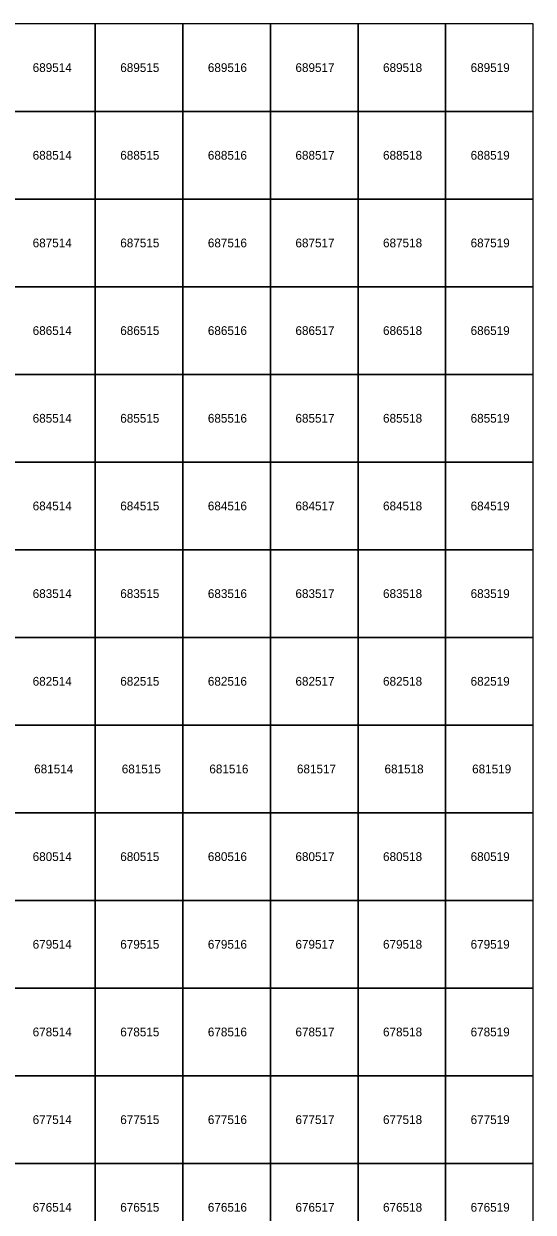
# Model space of a CAD drawing. Extents: x 25485000 to 25520000, y 6656775 to 6690000.
# Drawn here: x 25514183 to 25520000, y 6676444 to 6690000 of the extents above; entities that cross this region are included whole.
import ezdxf

# ---------------------------------------------------------------- set-up
doc = ezdxf.new("R2010")
doc.units = 0
doc.layers.add('Level 63', color=7, linetype='Continuous')

msp = doc.modelspace()

# ---------------------------------------------------------------- linework, layer by layer
at = {"layer": 'Level 63'}
for points in [[(25514000, 6689000), (25515000, 6689000), (25515000, 6690000), (25514000, 6690000)], [(25515000, 6689000), (25516000, 6689000), (25516000, 6690000), (25515000, 6690000)], [(25516000, 6689000), (25517000, 6689000), (25517000, 6690000), (25516000, 6690000)], [(25517000, 6689000), (25518000, 6689000), (25518000, 6690000), (25517000, 6690000)], [(25518000, 6689000), (25519000, 6689000), (25519000, 6690000), (25518000, 6690000)], [(25519000, 6689000), (25520000, 6689000), (25520000, 6690000), (25519000, 6690000)], [(25514000, 6688000), (25515000, 6688000), (25515000, 6689000), (25514000, 6689000)], [(25515000, 6688000), (25516000, 6688000), (25516000, 6689000), (25515000, 6689000)], [(25516000, 6688000), (25517000, 6688000), (25517000, 6689000), (25516000, 6689000)], [(25517000, 6688000), (25518000, 6688000), (25518000, 6689000), (25517000, 6689000)], [(25518000, 6688000), (25519000, 6688000), (25519000, 6689000), (25518000, 6689000)], [(25519000, 6688000), (25520000, 6688000), (25520000, 6689000), (25519000, 6689000)], [(25514000, 6687000), (25515000, 6687000), (25515000, 6688000), (25514000, 6688000)], [(25515000, 6687000), (25516000, 6687000), (25516000, 6688000), (25515000, 6688000)], [(25516000, 6687000), (25517000, 6687000), (25517000, 6688000), (25516000, 6688000)], [(25517000, 6687000), (25518000, 6687000), (25518000, 6688000), (25517000, 6688000)], [(25518000, 6687000), (25519000, 6687000), (25519000, 6688000), (25518000, 6688000)], [(25519000, 6687000), (25520000, 6687000), (25520000, 6688000), (25519000, 6688000)], [(25514000, 6686000), (25515000, 6686000), (25515000, 6687000), (25514000, 6687000)], [(25515000, 6686000), (25516000, 6686000), (25516000, 6687000), (25515000, 6687000)], [(25516000, 6686000), (25517000, 6686000), (25517000, 6687000), (25516000, 6687000)], [(25517000, 6686000), (25518000, 6686000), (25518000, 6687000), (25517000, 6687000)], [(25518000, 6686000), (25519000, 6686000), (25519000, 6687000), (25518000, 6687000)], [(25519000, 6686000), (25520000, 6686000), (25520000, 6687000), (25519000, 6687000)], [(25514000, 6685000), (25515000, 6685000), (25515000, 6686000), (25514000, 6686000)], [(25515000, 6685000), (25516000, 6685000), (25516000, 6686000), (25515000, 6686000)], [(25516000, 6685000), (25517000, 6685000), (25517000, 6686000), (25516000, 6686000)], [(25517000, 6685000), (25518000, 6685000), (25518000, 6686000), (25517000, 6686000)], [(25518000, 6685000), (25519000, 6685000), (25519000, 6686000), (25518000, 6686000)], [(25519000, 6685000), (25520000, 6685000), (25520000, 6686000), (25519000, 6686000)], [(25514000, 6684000), (25515000, 6684000), (25515000, 6685000), (25514000, 6685000)], [(25515000, 6684000), (25516000, 6684000), (25516000, 6685000), (25515000, 6685000)], [(25516000, 6684000), (25517000, 6684000), (25517000, 6685000), (25516000, 6685000)], [(25517000, 6684000), (25518000, 6684000), (25518000, 6685000), (25517000, 6685000)], [(25518000, 6684000), (25519000, 6684000), (25519000, 6685000), (25518000, 6685000)], [(25519000, 6684000), (25520000, 6684000), (25520000, 6685000), (25519000, 6685000)], [(25514000, 6683000), (25515000, 6683000), (25515000, 6684000), (25514000, 6684000)], [(25515000, 6683000), (25516000, 6683000), (25516000, 6684000), (25515000, 6684000)], [(25516000, 6683000), (25517000, 6683000), (25517000, 6684000), (25516000, 6684000)], [(25517000, 6683000), (25518000, 6683000), (25518000, 6684000), (25517000, 6684000)], [(25518000, 6683000), (25519000, 6683000), (25519000, 6684000), (25518000, 6684000)], [(25519000, 6683000), (25520000, 6683000), (25520000, 6684000), (25519000, 6684000)], [(25514000, 6682000), (25515000, 6682000), (25515000, 6683000), (25514000, 6683000)], [(25515000, 6682000), (25516000, 6682000), (25516000, 6683000), (25515000, 6683000)], [(25516000, 6682000), (25517000, 6682000), (25517000, 6683000), (25516000, 6683000)], [(25517000, 6682000), (25518000, 6682000), (25518000, 6683000), (25517000, 6683000)], [(25518000, 6682000), (25519000, 6682000), (25519000, 6683000), (25518000, 6683000)], [(25519000, 6682000), (25520000, 6682000), (25520000, 6683000), (25519000, 6683000)], [(25514000, 6681000), (25515000, 6681000), (25515000, 6682000), (25514000, 6682000)], [(25515000, 6681000), (25516000, 6681000), (25516000, 6682000), (25515000, 6682000)], [(25516000, 6681000), (25517000, 6681000), (25517000, 6682000), (25516000, 6682000)], [(25517000, 6681000), (25518000, 6681000), (25518000, 6682000), (25517000, 6682000)], [(25518000, 6681000), (25519000, 6681000), (25519000, 6682000), (25518000, 6682000)], [(25519000, 6681000), (25520000, 6681000), (25520000, 6682000), (25519000, 6682000)], [(25514000, 6680000), (25515000, 6680000), (25515000, 6681000), (25514000, 6681000)], [(25515000, 6680000), (25516000, 6680000), (25516000, 6681000), (25515000, 6681000)], [(25516000, 6680000), (25517000, 6680000), (25517000, 6681000), (25516000, 6681000)], [(25517000, 6680000), (25518000, 6680000), (25518000, 6681000), (25517000, 6681000)], [(25518000, 6680000), (25519000, 6680000), (25519000, 6681000), (25518000, 6681000)], [(25519000, 6680000), (25520000, 6680000), (25520000, 6681000), (25519000, 6681000)], [(25514000, 6679000), (25515000, 6679000), (25515000, 6680000), (25514000, 6680000)], [(25515000, 6679000), (25516000, 6679000), (25516000, 6680000), (25515000, 6680000)], [(25516000, 6679000), (25517000, 6679000), (25517000, 6680000), (25516000, 6680000)], [(25517000, 6679000), (25518000, 6679000), (25518000, 6680000), (25517000, 6680000)], [(25518000, 6679000), (25519000, 6679000), (25519000, 6680000), (25518000, 6680000)], [(25519000, 6679000), (25520000, 6679000), (25520000, 6680000), (25519000, 6680000)], [(25514000, 6678000), (25515000, 6678000), (25515000, 6679000), (25514000, 6679000)], [(25515000, 6678000), (25516000, 6678000), (25516000, 6679000), (25515000, 6679000)], [(25516000, 6678000), (25517000, 6678000), (25517000, 6679000), (25516000, 6679000)], [(25517000, 6678000), (25518000, 6678000), (25518000, 6679000), (25517000, 6679000)], [(25518000, 6678000), (25519000, 6678000), (25519000, 6679000), (25518000, 6679000)], [(25519000, 6678000), (25520000, 6678000), (25520000, 6679000), (25519000, 6679000)], [(25514000, 6677000), (25515000, 6677000), (25515000, 6678000), (25514000, 6678000)], [(25515000, 6677000), (25516000, 6677000), (25516000, 6678000), (25515000, 6678000)], [(25516000, 6677000), (25517000, 6677000), (25517000, 6678000), (25516000, 6678000)], [(25517000, 6677000), (25518000, 6677000), (25518000, 6678000), (25517000, 6678000)], [(25518000, 6677000), (25519000, 6677000), (25519000, 6678000), (25518000, 6678000)], [(25519000, 6677000), (25520000, 6677000), (25520000, 6678000), (25519000, 6678000)], [(25514000, 6676000), (25515000, 6676000), (25515000, 6677000), (25514000, 6677000)], [(25515000, 6676000), (25516000, 6676000), (25516000, 6677000), (25515000, 6677000)], [(25516000, 6676000), (25517000, 6676000), (25517000, 6677000), (25516000, 6677000)], [(25517000, 6676000), (25518000, 6676000), (25518000, 6677000), (25517000, 6677000)], [(25518000, 6676000), (25519000, 6676000), (25519000, 6677000), (25518000, 6677000)], [(25519000, 6676000), (25520000, 6676000), (25520000, 6677000), (25519000, 6677000)]]:
    msp.add_lwpolyline(points, close=True, dxfattribs=at)

# ---------------------------------------------------------------- texts
for s, p in [('689514', (25514285, 6689450)), ('689515', (25515285, 6689450)), ('689516', (25516285, 6689450)), ('689517', (25517285, 6689450)), ('689518', (25518285, 6689450)), ('689519', (25519285, 6689450)), ('688514', (25514285, 6688450)), ('688515', (25515285, 6688450)), ('688516', (25516285, 6688450)), ('688517', (25517285, 6688450)), ('688518', (25518285, 6688450)), ('688519', (25519285, 6688450)), ('687514', (25514285, 6687450)), ('687515', (25515285, 6687450)), ('687516', (25516285, 6687450)), ('687517', (25517285, 6687450)), ('687518', (25518285, 6687450)), ('687519', (25519285, 6687450)), ('686514', (25514285, 6686450)), ('686515', (25515285, 6686450)), ('686516', (25516285, 6686450)), ('686517', (25517285, 6686450)), ('686518', (25518285, 6686450)), ('686519', (25519285, 6686450)), ('685514', (25514285, 6685450)), ('685515', (25515285, 6685450)), ('685516', (25516285, 6685450)), ('685517', (25517285, 6685450)), ('685518', (25518285, 6685450)), ('685519', (25519285, 6685450)), ('684514', (25514285, 6684450)), ('684515', (25515285, 6684450)), ('684516', (25516285, 6684450)), ('684517', (25517285, 6684450)), ('684518', (25518285, 6684450)), ('684519', (25519285, 6684450)), ('683514', (25514285, 6683450)), ('683515', (25515285, 6683450)), ('683516', (25516285, 6683450)), ('683517', (25517285, 6683450)), ('683518', (25518285, 6683450)), ('683519', (25519285, 6683450)), ('682514', (25514285, 6682450)), ('682515', (25515285, 6682450)), ('682516', (25516285, 6682450)), ('682517', (25517285, 6682450)), ('682518', (25518285, 6682450)), ('682519', (25519285, 6682450)), ('681514', (25514302, 6681450)), ('681515', (25515302, 6681450)), ('681516', (25516302, 6681450)), ('681517', (25517302, 6681450)), ('681518', (25518302, 6681450)), ('681519', (25519302, 6681450)), ('680514', (25514285, 6680450)), ('680515', (25515285, 6680450)), ('680516', (25516285, 6680450)), ('680517', (25517285, 6680450)), ('680518', (25518285, 6680450)), ('680519', (25519285, 6680450)), ('679514', (25514285, 6679450)), ('679515', (25515285, 6679450)), ('679516', (25516285, 6679450)), ('679517', (25517285, 6679450)), ('679518', (25518285, 6679450)), ('679519', (25519285, 6679450)), ('678514', (25514285, 6678450)), ('678515', (25515285, 6678450)), ('678516', (25516285, 6678450)), ('678517', (25517285, 6678450)), ('678518', (25518285, 6678450)), ('678519', (25519285, 6678450)), ('677514', (25514285, 6677450)), ('677515', (25515285, 6677450)), ('677516', (25516285, 6677450)), ('677517', (25517285, 6677450)), ('677518', (25518285, 6677450)), ('677519', (25519285, 6677450)), ('676514', (25514285, 6676450)), ('676515', (25515285, 6676450)), ('676516', (25516285, 6676450)), ('676517', (25517285, 6676450)), ('676518', (25518285, 6676450)), ('676519', (25519285, 6676450))]:
    msp.add_text(s, height=100, dxfattribs=at).set_placement(p)

doc.saveas('drawing.dxf')
